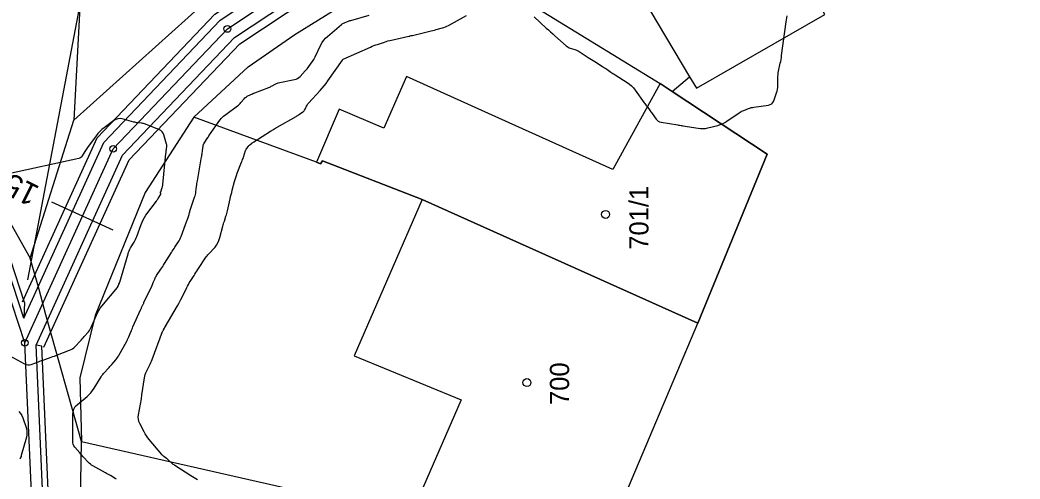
# Model space of a CAD drawing. Extents: x -534481 to -534262, y -1190577 to -1190138.
# Drawn here: x -534410.08 to -534365.66, y -1190397.49 to -1190377.09 of the extents above; entities that cross this region are included whole.
import ezdxf

# ---------------------------------------------------------------- set-up
doc = ezdxf.new("R2010")
doc.units = 0
for name, color, linetype in [('Bonity', 7, 'Continuous'), ('Definiční body', 7, 'Continuous'), ('Polygon budovy', 7, 'Continuous'), ('Polygon parcely', 7, 'Continuous'), ('Vrstva 18', 7, 'Continuous'), ('Vrstva 19', 7, 'Continuous'), ('Vrstva 31', 7, 'Continuous'), ('Vrstva 32', 7, 'Continuous'), ('Vrstva 35', 7, 'Continuous'), ('Vrstva 37', 7, 'Continuous'), ('Vrstva 46', 7, 'Continuous')]:
    doc.layers.add(name, color=color, linetype=linetype)

msp = doc.modelspace()

# ---------------------------------------------------------------- linework, layer by layer
at = {"layer": 'Bonity'}
for points in [[(-534409.868, -1190391.439), (-534405.947, -1190382.816), (-534400.873, -1190377.487), (-534393.696, -1190372.718), (-534384.927, -1190365.477), (-534382.631, -1190361.148), (-534355.894, -1190347.823), (-534351.738, -1190342.389), (-534351.577, -1190328.316), (-534347.204, -1190300.921), (-534345.553, -1190283.64), (-534344.682, -1190264.494)], [(-534409.868, -1190391.439), (-534411.855, -1190385.422)], [(-534408.105, -1190518.46), (-534393.616, -1190502.389), (-534391.346, -1190496.962), (-534392.763, -1190488.017), (-534396.655, -1190477.752), (-534402.513, -1190464.283), (-534404.757, -1190456.741), (-534408.311, -1190433.088), (-534409.248, -1190427.879), (-534409.316, -1190416.054), (-534409.076, -1190409.418), (-534409.868, -1190391.439)]]:
    msp.add_lwpolyline(points, dxfattribs=at)
at = {"layer": 'Definiční body'}
for p, q in [((-534409.63, -1190387.68), (-534407.69, -1190381.54)), ((-534407.5, -1190405.6), (-534407.36, -1190395.83)), ((-534407.36, -1190395.83), (-534397.83, -1190397.99))]:
    msp.add_line(p, q, dxfattribs=at)
for points in [[(-534425.49, -1190303.95), (-534427.4, -1190310.23), (-534432.23, -1190329.13), (-534431.92, -1190332.1), (-534423.51, -1190345.02), (-534415.2, -1190368.18), (-534411.18, -1190384.97), (-534409.63, -1190387.68)], [(-534403.65, -1190306.96), (-534404.41, -1190319.66), (-534407.69, -1190381.54)], [(-534407.69, -1190381.54), (-534401.89, -1190376.32), (-534395.25, -1190371.93), (-534386.83, -1190364.89)], [(-534402.36, -1190381.41), (-534399.95, -1190379.17), (-534397.88, -1190377.73), (-534391.57, -1190373.81)], [(-534389.87, -1190374.86), (-534381.65, -1190379.91), (-534381.11, -1190380.27)], [(-534381.11, -1190380.27), (-534380.34, -1190379.62), (-534380.04, -1190380.12), (-534376.63, -1190378.16), (-534374.33, -1190376.84)], [(-534381.11, -1190380.27), (-534376.9, -1190383.06), (-534379.97, -1190390.57)], [(-534402.36, -1190381.41), (-534404.53, -1190384.76), (-534406.75, -1190390.22), (-534407.43, -1190393), (-534407.36, -1190395.83)], [(-534379.97, -1190390.57), (-534392.22, -1190385.07), (-534396.64, -1190383.35), (-534396.74, -1190383.48), (-534396.92, -1190383.41), (-534402.36, -1190381.41)], [(-534407.36, -1190395.83), (-534408.93, -1190390.19), (-534409.24, -1190389.07), (-534409.63, -1190387.68)], [(-534397.83, -1190397.99), (-534392.73, -1190399.11), (-534384.27, -1190400.73), (-534379.97, -1190390.57)]]:
    msp.add_lwpolyline(points, dxfattribs=at)
at = {"layer": 'Polygon parcely'}
for points in [[(-534380.29, -1190367.33), (-534384.01, -1190370.07), (-534380.46, -1190374.87), (-534382.43, -1190376.09), (-534380.34, -1190379.62), (-534380.04, -1190380.12), (-534376.63, -1190378.16), (-534374.33, -1190376.84), (-534376.6, -1190372.66)], [(-534396.92, -1190383.41), (-534396.74, -1190383.48), (-534396.64, -1190383.35), (-534392.22, -1190385.07), (-534379.97, -1190390.57), (-534376.9, -1190383.06), (-534381.11, -1190380.27), (-534381.65, -1190379.91), (-534382.92, -1190382.23), (-534383.75, -1190383.73), (-534388.06, -1190381.79), (-534392.92, -1190379.6), (-534393.92, -1190381.89), (-534395.9, -1190381.05)], [(-534392.73, -1190399.11), (-534384.27, -1190400.73), (-534379.97, -1190390.57), (-534392.22, -1190385.07), (-534395.24, -1190392.02), (-534390.48, -1190393.97)]]:
    msp.add_lwpolyline(points, close=True, dxfattribs=at)
at = {"layer": 'Vrstva 18'}
for points in [[(-534405.799, -1190397.504), (-534405.852, -1190397.471), (-534406.071, -1190397.344), (-534406.125, -1190397.313), (-534406.18, -1190397.282), (-534406.235, -1190397.251), (-534406.29, -1190397.22), (-534406.847, -1190396.911), (-534406.905, -1190396.876), (-534406.96, -1190396.836), (-534407.011, -1190396.792), (-534407.059, -1190396.743), (-534407.245, -1190396.54), (-534407.291, -1190396.489), (-534407.336, -1190396.438), (-534407.381, -1190396.386), (-534407.426, -1190396.334), (-534407.642, -1190396.079), (-534407.686, -1190396.016), (-534407.718, -1190395.95), (-534407.737, -1190395.878), (-534407.743, -1190395.802), (-534407.743, -1190394.625), (-534407.73, -1190394.497), (-534407.692, -1190394.381), (-534407.627, -1190394.277), (-534407.537, -1190394.185), (-534407.105, -1190393.823), (-534407.016, -1190393.742), (-534406.935, -1190393.655), (-534406.86, -1190393.562), (-534406.794, -1190393.462), (-534406.477, -1190392.946), (-534406.445, -1190392.896), (-534406.41, -1190392.848), (-534406.373, -1190392.802), (-534406.333, -1190392.758), (-534406.169, -1190392.586), (-534406.129, -1190392.543), (-534406.089, -1190392.499), (-534406.05, -1190392.454), (-534406.011, -1190392.409), (-534405.829, -1190392.193), (-534405.788, -1190392.141), (-534405.749, -1190392.087), (-534405.712, -1190392.031), (-534405.679, -1190391.974), (-534405.359, -1190391.391), (-534405.331, -1190391.338), (-534405.304, -1190391.285), (-534405.279, -1190391.231), (-534405.254, -1190391.176), (-534405.16, -1190390.955), (-534405.136, -1190390.9), (-534405.113, -1190390.845), (-534405.089, -1190390.79), (-534405.065, -1190390.735), (-534404.716, -1190389.942), (-534404.705, -1190389.918), (-534404.694, -1190389.894), (-534404.682, -1190389.87), (-534404.671, -1190389.846), (-534404.624, -1190389.75), (-534404.612, -1190389.726), (-534404.601, -1190389.702), (-534404.589, -1190389.678), (-534404.578, -1190389.654), (-534404.234, -1190388.923), (-534404.216, -1190388.884), (-534404.198, -1190388.844), (-534404.181, -1190388.804), (-534404.164, -1190388.764), (-534404.098, -1190388.603), (-534404.081, -1190388.563), (-534404.062, -1190388.524), (-534404.04, -1190388.486), (-534404.017, -1190388.45), (-534403.824, -1190388.162), (-534403.784, -1190388.102), (-534403.744, -1190388.042), (-534403.705, -1190387.981), (-534403.666, -1190387.92), (-534403.355, -1190387.424), (-534403.318, -1190387.365), (-534403.281, -1190387.307), (-534403.243, -1190387.249), (-534403.205, -1190387.191), (-534403.053, -1190386.96), (-534403.017, -1190386.901), (-534402.984, -1190386.841), (-534402.954, -1190386.779), (-534402.928, -1190386.715), (-534402.667, -1190386.018), (-534402.654, -1190385.983), (-534402.641, -1190385.947), (-534402.63, -1190385.911), (-534402.619, -1190385.875), (-534402.577, -1190385.73), (-534402.567, -1190385.694), (-534402.556, -1190385.658), (-534402.544, -1190385.622), (-534402.533, -1190385.586), (-534402.326, -1190384.96), (-534402.308, -1190384.902), (-534402.293, -1190384.843), (-534402.281, -1190384.784), (-534402.272, -1190384.724), (-534402.241, -1190384.483), (-534402.232, -1190384.423), (-534402.224, -1190384.363), (-534402.214, -1190384.303), (-534402.204, -1190384.243), (-534402.019, -1190383.175), (-534402.013, -1190383.142), (-534402.008, -1190383.109), (-534402.003, -1190383.076), (-534401.998, -1190383.043), (-534401.977, -1190382.895), (-534401.974, -1190382.87), (-534401.971, -1190382.844), (-534401.967, -1190382.819), (-534401.964, -1190382.794), (-534401.953, -1190382.692), (-534401.949, -1190382.667), (-534401.942, -1190382.642), (-534401.932, -1190382.619), (-534401.92, -1190382.597), (-534401.794, -1190382.398), (-534401.768, -1190382.357), (-534401.742, -1190382.317), (-534401.716, -1190382.277), (-534401.689, -1190382.238), (-534401.288, -1190381.647), (-534401.214, -1190381.547), (-534401.132, -1190381.455), (-534401.043, -1190381.369), (-534400.946, -1190381.291), (-534400.427, -1190380.908), (-534400.385, -1190380.875), (-534400.346, -1190380.84), (-534400.308, -1190380.803), (-534400.273, -1190380.763), (-534400.126, -1190380.589), (-534400.095, -1190380.556), (-534400.062, -1190380.527), (-534400.026, -1190380.502), (-534399.986, -1190380.48), (-534399.824, -1190380.4), (-534399.783, -1190380.38), (-534399.742, -1190380.361), (-534399.701, -1190380.344), (-534399.659, -1190380.327), (-534399.028, -1190380.085), (-534398.992, -1190380.07), (-534398.957, -1190380.054), (-534398.922, -1190380.037), (-534398.888, -1190380.018), (-534398.753, -1190379.941), (-534398.718, -1190379.923), (-534398.683, -1190379.908), (-534398.646, -1190379.896), (-534398.609, -1190379.887), (-534397.893, -1190379.74), (-534397.821, -1190379.719), (-534397.755, -1190379.689), (-534397.694, -1190379.648), (-534397.639, -1190379.597), (-534397.415, -1190379.355), (-534397.372, -1190379.307), (-534397.33, -1190379.258), (-534397.29, -1190379.208), (-534397.252, -1190379.156), (-534397.101, -1190378.948), (-534397.065, -1190378.896), (-534397.031, -1190378.841), (-534396.999, -1190378.786), (-534396.971, -1190378.728), (-534396.716, -1190378.192), (-534396.659, -1190378.087), (-534396.593, -1190377.99), (-534396.516, -1190377.901), (-534396.429, -1190377.819), (-534395.8, -1190377.284), (-534395.771, -1190377.261), (-534395.74, -1190377.24), (-534395.707, -1190377.223), (-534395.673, -1190377.208), (-534395.533, -1190377.152), (-534395.498, -1190377.139), (-534395.462, -1190377.127), (-534395.426, -1190377.115), (-534395.39, -1190377.105), (-534394.568, -1190376.878)], [(-534410.132, -1190394.497), (-534410.06, -1190394.578), (-534410.003, -1190394.669), (-534409.959, -1190394.772), (-534409.815, -1190395.204), (-534409.787, -1190395.312), (-534409.776, -1190395.42), (-534409.781, -1190395.529), (-534409.803, -1190395.639), (-534410.026, -1190396.451), (-534410.039, -1190396.494), (-534410.056, -1190396.535), (-534410.075, -1190396.576), (-534410.098, -1190396.615)]]:
    msp.add_lwpolyline(points, dxfattribs=at)
at = {"layer": 'Vrstva 19'}
for points in [[(-534402.195, -1190397.53), (-534402.27, -1190397.488), (-534402.345, -1190397.445), (-534402.418, -1190397.4), (-534402.49, -1190397.354), (-534403.208, -1190396.889), (-534403.242, -1190396.866), (-534403.275, -1190396.842), (-534403.308, -1190396.816), (-534403.339, -1190396.789), (-534403.47, -1190396.67), (-534403.496, -1190396.647), (-534403.523, -1190396.624), (-534403.55, -1190396.602), (-534403.577, -1190396.581), (-534403.688, -1190396.497), (-534403.715, -1190396.475), (-534403.74, -1190396.452), (-534403.765, -1190396.427), (-534403.788, -1190396.401), (-534404.345, -1190395.738), (-534404.409, -1190395.657), (-534404.468, -1190395.573), (-534404.523, -1190395.486), (-534404.572, -1190395.396), (-534404.761, -1190395.028), (-534404.8, -1190394.935), (-534404.823, -1190394.84), (-534404.829, -1190394.742), (-534404.819, -1190394.641), (-534404.69, -1190393.934), (-534404.688, -1190393.918), (-534404.686, -1190393.903), (-534404.684, -1190393.887), (-534404.682, -1190393.871), (-534404.678, -1190393.808), (-534404.676, -1190393.793), (-534404.675, -1190393.777), (-534404.673, -1190393.761), (-534404.671, -1190393.746), (-534404.557, -1190392.99), (-534404.543, -1190392.918), (-534404.523, -1190392.848), (-534404.499, -1190392.78), (-534404.468, -1190392.713), (-534404.335, -1190392.451), (-534404.303, -1190392.384), (-534404.272, -1190392.318), (-534404.243, -1190392.25), (-534404.216, -1190392.181), (-534403.748, -1190390.942), (-534403.746, -1190390.934), (-534403.743, -1190390.928), (-534403.739, -1190390.921), (-534403.736, -1190390.914), (-534403.721, -1190390.887), (-534403.714, -1190390.874), (-534403.707, -1190390.861), (-534403.671, -1190390.787), (-534403.664, -1190390.773), (-534403.656, -1190390.759), (-534403.649, -1190390.744), (-534403.641, -1190390.73), (-534403.089, -1190389.789), (-534403.036, -1190389.697), (-534402.985, -1190389.604), (-534402.935, -1190389.511), (-534402.888, -1190389.416), (-534402.675, -1190388.985), (-534402.639, -1190388.915), (-534402.602, -1190388.847), (-534402.563, -1190388.779), (-534402.522, -1190388.713), (-534402.355, -1190388.449), (-534402.313, -1190388.383), (-534402.27, -1190388.317), (-534402.227, -1190388.252), (-534402.184, -1190388.187), (-534401.809, -1190387.622), (-534401.775, -1190387.573), (-534401.738, -1190387.526), (-534401.699, -1190387.481), (-534401.658, -1190387.438), (-534401.471, -1190387.252), (-534401.439, -1190387.217), (-534401.409, -1190387.18), (-534401.383, -1190387.141), (-534401.359, -1190387.099), (-534401.271, -1190386.929), (-534401.25, -1190386.886), (-534401.231, -1190386.843), (-534401.215, -1190386.798), (-534401.202, -1190386.752), (-534401.073, -1190386.259), (-534401.057, -1190386.201), (-534401.041, -1190386.144), (-534401.024, -1190386.087), (-534401.006, -1190386.03), (-534400.934, -1190385.804), (-534400.916, -1190385.747), (-534400.9, -1190385.689), (-534400.885, -1190385.632), (-534400.871, -1190385.574), (-534400.75, -1190385.036), (-534400.728, -1190384.941), (-534400.705, -1190384.845), (-534400.681, -1190384.75), (-534400.656, -1190384.655), (-534400.554, -1190384.275), (-534400.527, -1190384.18), (-534400.498, -1190384.087), (-534400.466, -1190383.994), (-534400.431, -1190383.902), (-534400.239, -1190383.408), (-534400.218, -1190383.352), (-534400.197, -1190383.296), (-534400.178, -1190383.24), (-534400.159, -1190383.184), (-534400.065, -1190382.896), (-534400.056, -1190382.871), (-534400.044, -1190382.847), (-534400.031, -1190382.823), (-534400.015, -1190382.801), (-534399.95, -1190382.714), (-534399.933, -1190382.693), (-534399.915, -1190382.673), (-534399.895, -1190382.654), (-534399.875, -1190382.636), (-534399.787, -1190382.566), (-534399.765, -1190382.549), (-534399.742, -1190382.532), (-534399.719, -1190382.517), (-534399.696, -1190382.501), (-534398.951, -1190382.034), (-534398.927, -1190382.019), (-534398.902, -1190382.004), (-534398.878, -1190381.988), (-534398.854, -1190381.972), (-534398.757, -1190381.91), (-534398.733, -1190381.895), (-534398.708, -1190381.88), (-534398.684, -1190381.865), (-534398.659, -1190381.85), (-534397.819, -1190381.372), (-534397.781, -1190381.35), (-534397.744, -1190381.327), (-534397.708, -1190381.303), (-534397.672, -1190381.279), (-534397.523, -1190381.175), (-534397.492, -1190381.151), (-534397.466, -1190381.123), (-534397.443, -1190381.092), (-534397.423, -1190381.058), (-534397.354, -1190380.916), (-534397.335, -1190380.881), (-534397.314, -1190380.848), (-534397.291, -1190380.816), (-534397.266, -1190380.786), (-534396.754, -1190380.228), (-534396.661, -1190380.124), (-534396.573, -1190380.016), (-534396.488, -1190379.906), (-534396.406, -1190379.793), (-534395.765, -1190378.869), (-534395.759, -1190378.861), (-534395.753, -1190378.855), (-534395.74, -1190378.842), (-534395.737, -1190378.838), (-534395.733, -1190378.836), (-534395.729, -1190378.833), (-534395.725, -1190378.831), (-534394.513, -1190378.291), (-534394.438, -1190378.258), (-534394.362, -1190378.228), (-534394.285, -1190378.199), (-534394.208, -1190378.173), (-534393.898, -1190378.07), (-534393.82, -1190378.045), (-534393.742, -1190378.022), (-534393.663, -1190378.002), (-534393.584, -1190377.983), (-534392.807, -1190377.813), (-534392.794, -1190377.81), (-534392.781, -1190377.806), (-534392.768, -1190377.803), (-534392.755, -1190377.799), (-534392.702, -1190377.785), (-534392.689, -1190377.781), (-534392.676, -1190377.778), (-534392.663, -1190377.774), (-534392.65, -1190377.771), (-534391.884, -1190377.586), (-534391.814, -1190377.569), (-534391.743, -1190377.551), (-534391.673, -1190377.534), (-534391.602, -1190377.516), (-534391.321, -1190377.444), (-534391.251, -1190377.424), (-534391.183, -1190377.399), (-534391.117, -1190377.37), (-534391.053, -1190377.337), (-534390.246, -1190376.885)], [(-534387.243, -1190376.949), (-534386.709, -1190377.445), (-534386.614, -1190377.533), (-534386.518, -1190377.62), (-534386.422, -1190377.706), (-534386.325, -1190377.792), (-534385.823, -1190378.236), (-534385.782, -1190378.269), (-534385.738, -1190378.297), (-534385.691, -1190378.321), (-534385.641, -1190378.339), (-534385.436, -1190378.403), (-534385.386, -1190378.421), (-534385.337, -1190378.442), (-534385.29, -1190378.466), (-534385.244, -1190378.494), (-534384.846, -1190378.75), (-534384.773, -1190378.797), (-534384.7, -1190378.844), (-534384.627, -1190378.891), (-534384.554, -1190378.937), (-534384.208, -1190379.155), (-534384.161, -1190379.185), (-534384.114, -1190379.216), (-534384.067, -1190379.246), (-534384.021, -1190379.277), (-534383.836, -1190379.403), (-534383.789, -1190379.434), (-534383.743, -1190379.465), (-534383.696, -1190379.495), (-534383.649, -1190379.525), (-534383.112, -1190379.869), (-534383.011, -1190379.94), (-534382.918, -1190380.02), (-534382.833, -1190380.109), (-534382.756, -1190380.206), (-534382.358, -1190380.764), (-534382.329, -1190380.804), (-534382.299, -1190380.844), (-534382.27, -1190380.885), (-534382.241, -1190380.925), (-534382.123, -1190381.085), (-534382.094, -1190381.125), (-534382.064, -1190381.166), (-534382.035, -1190381.206), (-534382.006, -1190381.246), (-534381.823, -1190381.496), (-534381.78, -1190381.546), (-534381.73, -1190381.584), (-534381.672, -1190381.612), (-534381.609, -1190381.629), (-534380.867, -1190381.751), (-534380.83, -1190381.758), (-534380.793, -1190381.764), (-534380.718, -1190381.776), (-534380.68, -1190381.782), (-534380.643, -1190381.788), (-534379.965, -1190381.902), (-534379.854, -1190381.915), (-534379.744, -1190381.916), (-534379.634, -1190381.906), (-534379.525, -1190381.884), (-534379.089, -1190381.772), (-534378.982, -1190381.74), (-534378.88, -1190381.698), (-534378.781, -1190381.648), (-534378.686, -1190381.589), (-534378.143, -1190381.214), (-534378.094, -1190381.183), (-534378.043, -1190381.154), (-534377.991, -1190381.128), (-534377.937, -1190381.106), (-534377.718, -1190381.021), (-534377.663, -1190381.002), (-534377.607, -1190380.986), (-534377.55, -1190380.973), (-534377.492, -1190380.963), (-534376.841, -1190380.87), (-534376.759, -1190380.848), (-534376.692, -1190380.809), (-534376.64, -1190380.751), (-534376.602, -1190380.676), (-534376.473, -1190380.324), (-534376.448, -1190380.247), (-534376.431, -1190380.169), (-534376.42, -1190380.089), (-534376.417, -1190380.008), (-534376.417, -1190379.681), (-534376.414, -1190379.6), (-534376.408, -1190379.519), (-534376.398, -1190379.438), (-534376.383, -1190379.358), (-534376.31, -1190379.013), (-534376.293, -1190378.929), (-534376.277, -1190378.844), (-534376.263, -1190378.759), (-534376.251, -1190378.674), (-534376.046, -1190377.175), (-534375.999, -1190376.898)], [(-534410.541, -1190392.024), (-534409.888, -1190392.376), (-534409.815, -1190392.406), (-534409.741, -1190392.42), (-534409.665, -1190392.417), (-534409.589, -1190392.397), (-534409.268, -1190392.28), (-534409.198, -1190392.254), (-534409.127, -1190392.229), (-534409.056, -1190392.204), (-534408.985, -1190392.179), (-534408.7, -1190392.079), (-534408.629, -1190392.054), (-534408.558, -1190392.029), (-534408.487, -1190392.003), (-534408.417, -1190391.976), (-534407.887, -1190391.771), (-534407.817, -1190391.74), (-534407.752, -1190391.702), (-534407.692, -1190391.657), (-534407.637, -1190391.604), (-534407.414, -1190391.371), (-534407.366, -1190391.32), (-534407.319, -1190391.268), (-534407.273, -1190391.216), (-534407.228, -1190391.163), (-534407.047, -1190390.951), (-534407.004, -1190390.896), (-534406.966, -1190390.839), (-534406.932, -1190390.779), (-534406.902, -1190390.716), (-534406.688, -1190390.203), (-534406.639, -1190390.099), (-534406.583, -1190389.998), (-534406.52, -1190389.903), (-534406.45, -1190389.811), (-534405.757, -1190388.976), (-534405.75, -1190388.967), (-534405.744, -1190388.958), (-534405.739, -1190388.949), (-534405.735, -1190388.939), (-534405.713, -1190388.887), (-534405.707, -1190388.874), (-534405.695, -1190388.849), (-534405.69, -1190388.836), (-534405.667, -1190388.781), (-534405.663, -1190388.771), (-534405.659, -1190388.76), (-534405.656, -1190388.749), (-534405.652, -1190388.738), (-534405.284, -1190387.484), (-534405.262, -1190387.415), (-534405.235, -1190387.348), (-534405.204, -1190387.283), (-534405.169, -1190387.22), (-534405.02, -1190386.97), (-534404.984, -1190386.906), (-534404.951, -1190386.842), (-534404.922, -1190386.775), (-534404.896, -1190386.708), (-534404.707, -1190386.182), (-534404.663, -1190386.073), (-534404.612, -1190385.969), (-534404.554, -1190385.868), (-534404.488, -1190385.771), (-534404.028, -1190385.145), (-534404.007, -1190385.116), (-534403.987, -1190385.087), (-534403.967, -1190385.057), (-534403.947, -1190385.027), (-534403.846, -1190384.866), (-534403.84, -1190384.855), (-534403.836, -1190384.844), (-534403.834, -1190384.832), (-534403.835, -1190384.82), (-534403.84, -1190384.77), (-534403.84, -1190384.758), (-534403.84, -1190384.746), (-534403.837, -1190384.734), (-534403.834, -1190384.722), (-534403.768, -1190384.542), (-534403.757, -1190384.508), (-534403.748, -1190384.473), (-534403.741, -1190384.438), (-534403.736, -1190384.402), (-534403.603, -1190383.024), (-534403.601, -1190383.006), (-534403.599, -1190382.988), (-534403.597, -1190382.97), (-534403.595, -1190382.952), (-534403.585, -1190382.88), (-534403.582, -1190382.862), (-534403.58, -1190382.844), (-534403.578, -1190382.827), (-534403.576, -1190382.809), (-534403.564, -1190382.706), (-534403.562, -1190382.683), (-534403.563, -1190382.66), (-534403.566, -1190382.638), (-534403.572, -1190382.615), (-534403.697, -1190382.188), (-534403.727, -1190382.116), (-534403.77, -1190382.055), (-534403.826, -1190382.007), (-534403.895, -1190381.97), (-534404.509, -1190381.724), (-534404.55, -1190381.709), (-534404.592, -1190381.697), (-534404.634, -1190381.688), (-534404.677, -1190381.681), (-534404.851, -1190381.66), (-534404.894, -1190381.654), (-534404.937, -1190381.647), (-534404.98, -1190381.638), (-534405.023, -1190381.627), (-534405.542, -1190381.488), (-534405.64, -1190381.472), (-534405.735, -1190381.479), (-534405.825, -1190381.507), (-534405.911, -1190381.558), (-534406.353, -1190381.882), (-534406.451, -1190381.96), (-534406.542, -1190382.045), (-534406.627, -1190382.137), (-534406.705, -1190382.235), (-534407.089, -1190382.758), (-534407.121, -1190382.801), (-534407.151, -1190382.846), (-534407.18, -1190382.891), (-534407.208, -1190382.938), (-534407.316, -1190383.124), (-534407.346, -1190383.166), (-534407.383, -1190383.2), (-534407.426, -1190383.224), (-534407.476, -1190383.24), (-534410.597, -1190383.921)]]:
    msp.add_lwpolyline(points, dxfattribs=at)
at = {"layer": 'Vrstva 31'}
for points in [[(-534409.732, -1190388.64), (-534397.101, -1190322.153), (-534346.296, -1190265.502)], [(-534405.94, -1190386.425), (-534408.672, -1190385.183)]]:
    msp.add_lwpolyline(points, dxfattribs=at)
at = {"layer": 'Vrstva 32'}
for p, q in [((-534409.879, -1190389.652), (-534409.916, -1190390.337)), ((-534409.111, -1190391.586), (-534409.363, -1190391.537))]:
    msp.add_line(p, q, dxfattribs=at)
for points in [[(-534409.97, -1190389.61), (-534406.662, -1190382.333), (-534401.423, -1190376.832), (-534394.204, -1190372.034), (-534385.599, -1190364.929), (-534383.254, -1190360.509), (-534356.45, -1190347.15), (-534352.584, -1190342.096), (-534352.426, -1190328.244), (-534348.048, -1190300.813), (-534346.401, -1190283.581), (-534345.607, -1190266.12)], [(-534409.916, -1190390.337), (-534406.368, -1190382.532), (-534401.196, -1190377.102), (-534393.995, -1190372.316), (-534385.322, -1190365.155), (-534382.997, -1190360.772), (-534356.221, -1190347.427), (-534352.236, -1190342.217), (-534352.076, -1190328.274), (-534347.7, -1190300.857), (-534346.052, -1190283.605), (-534345.255, -1190266.096)], [(-534409.363, -1190391.537), (-534405.527, -1190383.099), (-534400.549, -1190377.873), (-534393.398, -1190373.12), (-534384.532, -1190365.799), (-534382.264, -1190361.524), (-534355.568, -1190348.219), (-534351.24, -1190342.56), (-534351.077, -1190328.359), (-534346.708, -1190300.984), (-534345.054, -1190283.675), (-534344.256, -1190266.142)], [(-534409.02, -1190391.627), (-534405.233, -1190383.298), (-534400.323, -1190378.142), (-534393.189, -1190373.401), (-534384.256, -1190366.025), (-534382.008, -1190361.787), (-534355.339, -1190348.496), (-534350.891, -1190342.681), (-534350.728, -1190328.388), (-534346.36, -1190301.028), (-534344.705, -1190283.7), (-534343.908, -1190266.201)]]:
    msp.add_lwpolyline(points, dxfattribs=at)
at = {"layer": 'Vrstva 35'}
for points in [[(-534409.879, -1190389.652), (-534411.326, -1190385.272)], [(-534409.916, -1190390.337), (-534411.561, -1190385.357)], [(-534403.656, -1190514.273), (-534393.187, -1190502.661), (-534390.83, -1190497.024), (-534392.278, -1190487.888), (-534396.191, -1190477.563), (-534402.042, -1190464.111), (-534404.268, -1190456.632), (-534407.818, -1190433.007), (-534408.749, -1190427.833), (-534408.816, -1190416.061), (-534408.576, -1190409.416), (-534409.363, -1190391.537)], [(-534403.306, -1190514.257), (-534392.973, -1190502.796), (-534390.572, -1190497.055), (-534392.035, -1190487.824), (-534395.96, -1190477.469), (-534401.807, -1190464.025), (-534404.023, -1190456.578), (-534407.571, -1190432.966), (-534408.499, -1190427.81), (-534408.566, -1190416.065), (-534408.326, -1190409.415), (-534409.111, -1190391.586)]]:
    msp.add_lwpolyline(points, dxfattribs=at)
at = {"layer": 'Vrstva 37'}
for centre in [(-534400.873, -1190377.487), (-534400.873, -1190377.487), (-534400.873, -1190377.487), (-534400.873, -1190377.487), (-534400.873, -1190377.487), (-534400.873, -1190377.487), (-534405.947, -1190382.816), (-534405.947, -1190382.816), (-534405.947, -1190382.816), (-534405.947, -1190382.816), (-534405.947, -1190382.816), (-534405.947, -1190382.816), (-534409.868, -1190391.439), (-534409.868, -1190391.439), (-534409.868, -1190391.439), (-534409.868, -1190391.439), (-534409.868, -1190391.439), (-534409.868, -1190391.439)]:
    msp.add_circle(centre, 0.15, dxfattribs=at)
at = {"layer": 'Vrstva 46'}
for centre in [(-534384.072, -1190385.732), (-534387.566, -1190393.206)]:
    msp.add_circle(centre, 0.175, dxfattribs=at)

# ---------------------------------------------------------------- texts
at = {"layer": 'Polygon budovy'}
for s, p in [('701/1', (-534382.165, -1190387.303)), ('700', (-534385.694, -1190394.205))]:
    msp.add_text(s, height=0.85, rotation=90, dxfattribs=at).set_placement(p)
at = {"layer": 'Vrstva 31'}
msp.add_text('150', height=1, rotation=153.4033, dxfattribs=at).set_placement((-534409.166, -1190384.52))

doc.saveas('drawing.dxf')
